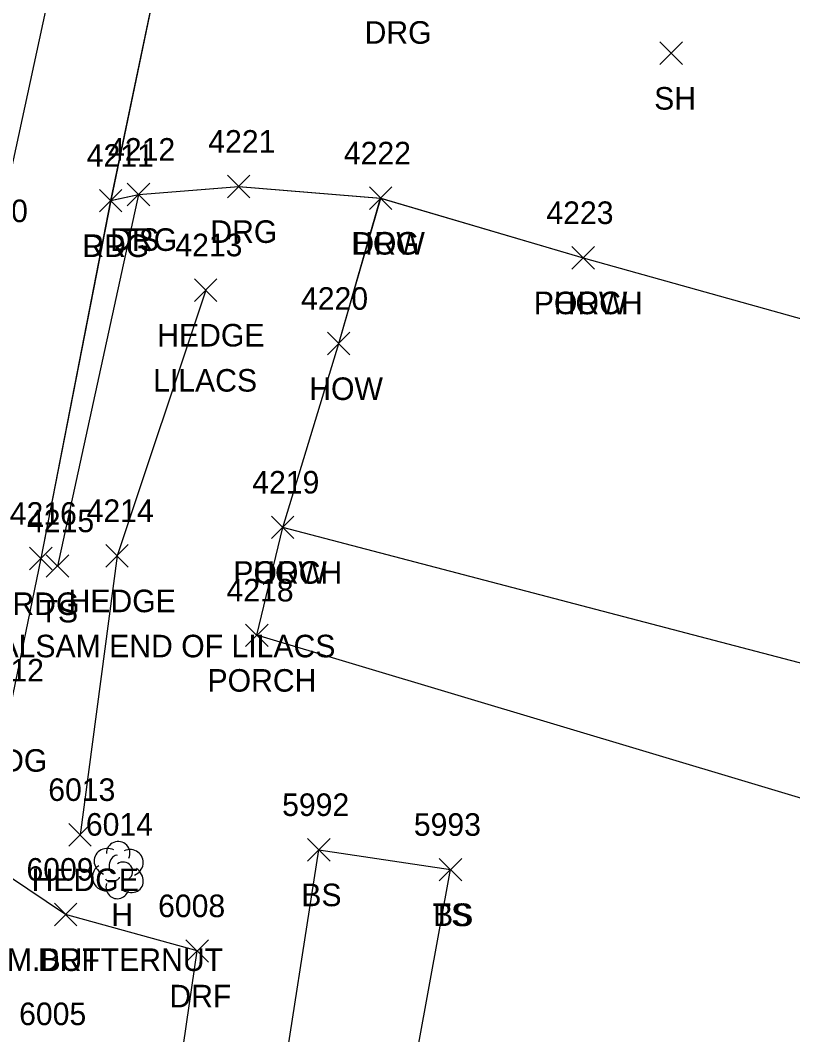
# Model space of a CAD drawing. Extents: x 1554668 to 1563881, y 831386 to 834374.
# Drawn here: x 1561957.7 to 1562026.2, y 834130.6 to 834220.5 of the extents above; entities that cross this region are included whole.
import ezdxf

# ---------------------------------------------------------------- set-up
doc = ezdxf.new("R2010")
doc.units = 0
for name, color, linetype in [('L_A', 7, 'Continuous'), ('L_C', 7, 'Continuous'), ('L_I', 7, 'Continuous'), ('L_TIC', 7, 'Continuous'), ('LAHR', 7, 'Continuous'), ('LBC', 7, 'Continuous'), ('LBF', 7, 'Continuous'), ('LELB', 7, 'Continuous'), ('LTD', 7, 'Continuous'), ('P_A', 7, 'Continuous'), ('P_I', 7, 'Continuous'), ('P_TIC', 7, 'Continuous'), ('PEU', 7, 'Continuous'), ('PRC', 7, 'Continuous'), ('R_A', 7, 'Continuous'), ('R_I', 7, 'Continuous'), ('R_TIC', 7, 'Continuous'), ('RDF', 7, 'Continuous'), ('RDG', 7, 'Continuous')]:
    doc.layers.add(name, color=color, linetype=linetype)

msp = doc.modelspace()

# ---------------------------------------------------------------- linework, layer by layer
at = {"layer": 'L_TIC'}
for points in [[(1562014.427, 834216.583), (1562016.427, 834218.583)], [(1562016.427, 834216.583), (1562014.427, 834218.583)], [(1561967.189, 834204.059), (1561969.189, 834206.059)], [(1561969.189, 834204.059), (1561967.189, 834206.059)], [(1561988.662, 834203.731), (1561990.662, 834205.731)], [(1561990.662, 834203.731), (1561988.662, 834205.731)], [(1562006.623, 834198.444), (1562008.623, 834200.444)], [(1562008.623, 834198.444), (1562006.623, 834200.444)], [(1562006.623, 834198.444), (1562008.623, 834200.444)], [(1562008.623, 834198.444), (1562006.623, 834200.444)], [(1561973.151, 834195.581), (1561975.151, 834197.581)], [(1561975.151, 834195.581), (1561973.151, 834197.581)], [(1561984.946, 834190.839), (1561986.946, 834192.839)], [(1561986.946, 834190.839), (1561984.946, 834192.839)], [(1561979.98, 834174.548), (1561981.98, 834176.548)], [(1561981.98, 834174.548), (1561979.98, 834176.548)], [(1561979.98, 834174.548), (1561981.98, 834176.548)], [(1561981.98, 834174.548), (1561979.98, 834176.548)], [(1561965.288, 834172.023), (1561967.288, 834174.023)], [(1561967.288, 834172.023), (1561965.288, 834174.023)], [(1561960.003, 834171.117), (1561962.003, 834173.117)], [(1561962.003, 834171.117), (1561960.003, 834173.117)], [(1561977.69, 834164.976), (1561979.69, 834166.976)], [(1561979.69, 834164.976), (1561977.69, 834166.976)], [(1561962.01, 834147.29), (1561964.01, 834149.29)], [(1561964.01, 834147.29), (1561962.01, 834149.29)], [(1561983.189, 834145.956), (1561985.189, 834147.956)], [(1561985.189, 834145.956), (1561983.189, 834147.956)], [(1561994.868, 834144.198), (1561996.868, 834146.198)], [(1561996.868, 834144.198), (1561994.868, 834146.198)], [(1561994.868, 834144.198), (1561996.868, 834146.198)], [(1561996.868, 834144.198), (1561994.868, 834146.198)]]:
    msp.add_lwpolyline(points, dxfattribs=at)
at = {"layer": 'LAHR'}
for points in [[(1561974.158, 834196.579), (1561966.294, 834173.02), (1561963.007, 834148.289)], [(1561974.158, 834196.579), (1561966.294, 834173.02), (1561963.007, 834148.289)], [(1561974.158, 834196.579), (1561966.294, 834173.02), (1561963.007, 834148.289)], [(1561974.151, 834196.581), (1561966.288, 834173.023), (1561963.01, 834148.29)]]:
    msp.add_lwpolyline(points, dxfattribs=at)
at = {"layer": 'LBC'}
for points in [[(1561980.98, 834175.548), (1561985.946, 834191.839), (1561989.662, 834204.731), (1562007.623, 834199.444)], [(1561980.987, 834175.546), (1561985.954, 834191.845), (1561989.67, 834204.731), (1562007.631, 834199.448)], [(1561980.987, 834175.546), (1561985.954, 834191.845), (1561989.67, 834204.731), (1562007.631, 834199.448)], [(1561980.987, 834175.546), (1561985.954, 834191.845), (1561989.67, 834204.731), (1562007.631, 834199.448)]]:
    msp.add_lwpolyline(points, dxfattribs=at)
at = {"layer": 'LBF'}
for points in [[(1562007.623, 834199.444), (1562031.735, 834192.714), (1562032.429, 834192.388)], [(1562007.631, 834199.448), (1562031.744, 834192.712), (1562032.437, 834192.39)], [(1562007.631, 834199.448), (1562031.744, 834192.712), (1562032.437, 834192.39)], [(1562007.631, 834199.448), (1562031.744, 834192.712), (1562032.437, 834192.39)], [(1561978.69, 834165.976), (1561980.98, 834175.548)], [(1561978.697, 834165.977), (1561980.987, 834175.546)], [(1561978.697, 834165.977), (1561980.987, 834175.546)], [(1561978.697, 834165.977), (1561980.987, 834175.546)], [(1562051.964, 834156.953), (1561980.98, 834175.548)], [(1562051.97, 834156.958), (1561980.987, 834175.546)], [(1562051.97, 834156.958), (1561980.987, 834175.546)], [(1562051.97, 834156.958), (1561980.987, 834175.546)], [(1562048.904, 834144.949), (1561978.69, 834165.976)], [(1562048.907, 834144.952), (1561978.697, 834165.977)], [(1562048.907, 834144.952), (1561978.697, 834165.977)], [(1562048.907, 834144.952), (1561978.697, 834165.977)]]:
    msp.add_lwpolyline(points, dxfattribs=at)
at = {"layer": 'LELB'}
for points in [[(1561968.189, 834205.059), (1561961.003, 834172.117)], [(1561968.198, 834205.062), (1561961.01, 834172.118)], [(1561968.198, 834205.062), (1561961.01, 834172.118)], [(1561968.198, 834205.062), (1561961.01, 834172.118)], [(1561964.208, 834009.165), (1561970.076, 834044.453), (1561977.705, 834089.291), (1561980.598, 834123.957), (1561984.189, 834146.956), (1561995.868, 834145.198)], [(1561964.212, 834009.164), (1561970.076, 834044.453), (1561977.706, 834089.291), (1561980.596, 834123.956), (1561984.186, 834146.955), (1561995.872, 834145.199)], [(1561964.212, 834009.164), (1561970.076, 834044.453), (1561977.706, 834089.291), (1561980.596, 834123.956), (1561984.186, 834146.955), (1561995.872, 834145.199)], [(1561964.212, 834009.164), (1561970.076, 834044.453), (1561977.706, 834089.291), (1561980.596, 834123.956), (1561984.186, 834146.955), (1561995.872, 834145.199)], [(1561972.837, 834001.403), (1561977.615, 834044.024), (1561983.41, 834089.696), (1561992.011, 834124.132), (1561995.872, 834145.199)], [(1561972.837, 834001.403), (1561977.615, 834044.024), (1561983.41, 834089.696), (1561992.011, 834124.132), (1561995.872, 834145.199)], [(1561972.837, 834001.403), (1561977.615, 834044.024), (1561983.41, 834089.696), (1561992.011, 834124.132), (1561995.872, 834145.199)], [(1561972.838, 834001.403), (1561977.619, 834044.023), (1561983.41, 834089.696), (1561992.013, 834124.133), (1561995.868, 834145.198)]]:
    msp.add_lwpolyline(points, dxfattribs=at)
at = {"layer": 'LTD'}
msp.add_line((1561966.344, 834145.212), (1561966.344, 834145.212), dxfattribs=at)
msp.add_line((1561966.344, 834145.212), (1561966.344, 834145.212), dxfattribs=at)
msp.add_arc((1561966.391, 834146.646), 1.047, 335.52715, 180.95627, dxfattribs=at)
for centre, major_axis, ratio, start_param, end_param in [((1561965.552, 834145.878), (1.21, -0.512), 0.895232, 1.570796, 4.712389), ((1561967.385, 834145.795), (-1.141, -0.483), 0.949671, 1.570796, 4.712389), ((1561966.135, 834145.67), (-0.208, -0.792), 0.645439, 3.141593, 6.283185), ((1561965.261, 834144.503), (0.584, -1.042), 0.959034, 3.141593, 6.283185), ((1561966.844, 834145.045), (-0.5, 0.667), 0.989748, 3.141593, 6.283185), ((1561967.344, 834144.379), (-1.09, 0.792), 0.841452, 1.570796, 4.712389), ((1561965.886, 834144.462), (-0.625, -0.083), 0.423636, 0, 3.141593), ((1561966.344, 834143.712), (0.265, 1.061), 0.942809, 1.570796, 4.712389)]:
    msp.add_ellipse(centre, major_axis=major_axis, ratio=ratio, start_param=start_param, end_param=end_param, dxfattribs=at)
at = {"layer": 'P_TIC'}
for points in [[(1561964.722, 834203.516), (1561966.722, 834205.516)], [(1561966.722, 834203.516), (1561964.722, 834205.516)], [(1561958.524, 834171.777), (1561960.524, 834173.777)], [(1561960.524, 834171.777), (1561958.524, 834173.777)]]:
    msp.add_lwpolyline(points, dxfattribs=at)
at = {"layer": 'PEU'}
for points in [[(1561993.867, 834247.497), (1561981.146, 834241.876), (1561971.829, 834233.783), (1561965.722, 834204.516), (1561959.524, 834172.777), (1561956.677, 834158.88)], [(1561993.875, 834247.495), (1561981.153, 834241.877), (1561971.838, 834233.787), (1561965.729, 834204.514), (1561959.533, 834172.782), (1561956.677, 834158.88)], [(1561993.875, 834247.495), (1561981.153, 834241.877), (1561971.838, 834233.787), (1561965.729, 834204.514), (1561959.533, 834172.782), (1561956.677, 834158.88)], [(1561993.875, 834247.495), (1561981.153, 834241.877), (1561971.838, 834233.787), (1561965.729, 834204.514), (1561959.533, 834172.782), (1561956.677, 834158.88)]]:
    msp.add_lwpolyline(points, dxfattribs=at)
at = {"layer": 'PRC'}
for points in [[(1561967.476, 834265.709), (1561963.045, 834235.77), (1561955.22, 834199.608), (1561950.815, 834174.788), (1561945.527, 834150.773)], [(1561967.476, 834265.709), (1561963.045, 834235.77), (1561955.22, 834199.608), (1561950.815, 834174.788), (1561945.527, 834150.773)], [(1561967.476, 834265.709), (1561963.045, 834235.77), (1561955.22, 834199.608), (1561950.815, 834174.788), (1561945.527, 834150.773)], [(1561967.469, 834265.707), (1561963.039, 834235.771), (1561955.213, 834199.609), (1561950.807, 834174.786), (1561945.529, 834150.774)]]:
    msp.add_lwpolyline(points, dxfattribs=at)
at = {"layer": 'R_TIC'}
for points in [[(1561976.072, 834204.768), (1561978.072, 834206.768)], [(1561978.072, 834204.768), (1561976.072, 834206.768)], [(1561964.722, 834203.516), (1561966.722, 834205.516)], [(1561966.722, 834203.516), (1561964.722, 834205.516)], [(1561967.189, 834204.059), (1561969.189, 834206.059)], [(1561969.189, 834204.059), (1561967.189, 834206.059)], [(1561967.189, 834204.059), (1561969.189, 834206.059)], [(1561969.189, 834204.059), (1561967.189, 834206.059)], [(1561988.662, 834203.731), (1561990.662, 834205.731)], [(1561990.662, 834203.731), (1561988.662, 834205.731)], [(1561960.731, 834140.224), (1561962.731, 834142.224)], [(1561962.731, 834140.224), (1561960.731, 834142.224)], [(1561972.395, 834136.986), (1561974.395, 834138.986)], [(1561974.395, 834136.986), (1561972.395, 834138.986)]]:
    msp.add_lwpolyline(points, dxfattribs=at)
at = {"layer": 'RDF'}
for points in [[(1561948.417, 834126.574), (1561953.536, 834128.252), (1561961.073, 834128.412), (1561971.48, 834124.79), (1561973.395, 834137.986), (1561961.731, 834141.224), (1561953.283, 834146.877)], [(1561948.419, 834126.576), (1561953.535, 834128.252), (1561961.072, 834128.412), (1561971.478, 834124.789), (1561973.394, 834137.986), (1561961.727, 834141.222), (1561953.285, 834146.878)], [(1561948.419, 834126.576), (1561953.535, 834128.252), (1561961.072, 834128.412), (1561971.478, 834124.789), (1561973.394, 834137.986), (1561961.727, 834141.222), (1561953.285, 834146.878)], [(1561948.419, 834126.576), (1561953.535, 834128.252), (1561961.072, 834128.412), (1561971.478, 834124.789), (1561973.394, 834137.986), (1561961.727, 834141.222), (1561953.285, 834146.878)]]:
    msp.add_lwpolyline(points, dxfattribs=at)
at = {"layer": 'RDG'}
for points in [[(1561968.189, 834205.059), (1561977.072, 834205.768), (1561989.662, 834204.731)], [(1561968.198, 834205.062), (1561977.081, 834205.773), (1561989.67, 834204.731)], [(1561968.198, 834205.062), (1561977.081, 834205.773), (1561989.67, 834204.731)], [(1561968.198, 834205.062), (1561977.081, 834205.773), (1561989.67, 834204.731)], [(1561965.722, 834204.516), (1561968.189, 834205.059)], [(1561965.729, 834204.514), (1561968.198, 834205.062)], [(1561965.729, 834204.514), (1561968.198, 834205.062)], [(1561965.729, 834204.514), (1561968.198, 834205.062)]]:
    msp.add_lwpolyline(points, dxfattribs=at)

# ---------------------------------------------------------------- texts
at = {"layer": 'L_A'}
for s, p in [('SH', (1562013.915, 834212.583)), ('TS', (1561966.598, 834200.059)), ('HOW', (1561987.048, 834199.731)), ('PORCH', (1562003.245, 834194.444)), ('HOW', (1562005.009, 834194.444)), ('HEDGE', (1561969.852, 834191.581)), ('HOW', (1561983.332, 834186.839)), ('PORCH', (1561976.602, 834170.548)), ('HOW', (1561978.365, 834170.548)), ('HEDGE', (1561961.989, 834168.023)), ('TS', (1561959.412, 834167.117)), ('PORCH', (1561974.312, 834160.976)), ('HEDGE', (1561958.711, 834143.29)), ('BS', (1561982.63, 834141.956)), ('H', (1561965.777, 834140.212)), ('TS', (1561994.278, 834140.198)), ('BS', (1561994.309, 834140.198))]:
    msp.add_text(s, height=2, dxfattribs=at).set_placement(p)
at = {"layer": 'L_C'}
for s, p in [('LILACS', (1561969.49, 834187.581)), ('BEG OF M.BALSAM END OF LILACS', (1561940.178, 834164.023)), ('M.BUTTERNUT', (1561956.525, 834136.212))]:
    msp.add_text(s, height=2, dxfattribs=at).set_placement(p)
at = {"layer": 'L_I'}
for s, p in [('4212', (1561965.496, 834208.059)), ('4222', (1561986.403, 834207.731)), ('4223', (1562004.363, 834202.444)), ('4223', (1562004.363, 834202.444)), ('4213', (1561971.458, 834199.581)), ('4220', (1561982.6, 834194.839)), ('4219', (1561978.279, 834178.548)), ('4219', (1561978.279, 834178.548)), ('4214', (1561963.595, 834176.023)), ('4215', (1561958.31, 834175.117)), ('4218', (1561975.997, 834168.976)), ('6013', (1561960.191, 834151.29)), ('5992', (1561980.929, 834149.956)), ('6014', (1561963.525, 834148.212)), ('5993', (1561992.609, 834148.198)), ('5993', (1561992.609, 834148.198)), ('6005', (1561957.608, 834131.412))]:
    msp.add_text(s, height=2, dxfattribs=at).set_placement(p)
at = {"layer": 'P_A'}
for p in [(1561963.21, 834199.516), (1561957.012, 834167.777), (1561954.165, 834153.88), (1561954.165, 834153.88)]:
    msp.add_text('RDG', height=2, dxfattribs=at).set_placement(p)
at = {"layer": 'P_I'}
for s, p in [('4211', (1561963.596, 834207.516)), ('4210', (1561952.433, 834202.609)), ('4216', (1561956.776, 834175.777)), ('6012', (1561953.858, 834161.88)), ('6012', (1561953.858, 834161.88))]:
    msp.add_text(s, height=2, dxfattribs=at).set_placement(p)
at = {"layer": 'R_A'}
for s, p in [('DRG', (1561988.239, 834218.427)), ('DRG', (1561974.56, 834200.768)), ('DRG', (1561965.677, 834200.059)), ('DRG', (1561965.677, 834200.059)), ('DRG', (1561963.21, 834199.516)), ('DRG', (1561987.151, 834199.731)), ('DRF', (1561959.267, 834136.224)), ('DRF', (1561970.931, 834132.986))]:
    msp.add_text(s, height=2, dxfattribs=at).set_placement(p)
at = {"layer": 'R_I'}
for s, p in [('4212', (1561965.496, 834208.059)), ('4212', (1561965.496, 834208.059)), ('4221', (1561974.379, 834208.768)), ('4211', (1561963.596, 834207.516)), ('4222', (1561986.403, 834207.731)), ('6009', (1561958.259, 834144.224)), ('6008', (1561969.931, 834140.986)), ('6005', (1561957.608, 834131.412))]:
    msp.add_text(s, height=2, dxfattribs=at).set_placement(p)

doc.saveas('drawing.dxf')
